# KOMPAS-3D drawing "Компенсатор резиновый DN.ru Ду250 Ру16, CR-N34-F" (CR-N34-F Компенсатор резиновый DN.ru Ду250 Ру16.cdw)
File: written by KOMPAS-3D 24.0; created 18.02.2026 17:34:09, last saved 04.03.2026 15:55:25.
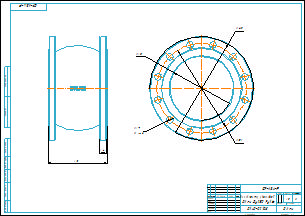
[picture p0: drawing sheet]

Document properties: Типовые: Типовые; Автор: DN.RU; Форматы листов документа: A2; Полное имя файла: CR-N34-F Компенсатор резиновый DN.ru Ду250 Ру16.m3d; Масса: 25; Наименование: Компенсатор резиновый DN.ru Ду250 Ру16; Количество листов документа: 1; Комментарий: D140-02108; Примечание: D140-02108

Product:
- Body: Твердое тело2  | qty 1
    Масса: 70.952857
- Part/product: Компенсатор резиновый DN.ru Ду250 Ру16  | designation CR-N34-F
    Масса: 25
    Раздел спецификации: Прочие изделия
    Комментарий: D140-02108
    Примечание: D140-02108
    additional columns: Типовые

Views: Вид 1, Спереди, Проекционный вид 2
Referenced files in E:\Работа\Зайцев\CR-N34-F Компенсатор резиновый DN.ru ДУ25-300 Ру10-16\DN250_PN16\: CR-N34-F Компенсатор резиновый DN.ru Ду250 Ру16.m3d
Referenced files in E:\Работа\Зайцев\Для компаса\: чертеж DN.ru А3.cdt
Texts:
  CR-N34-F
  чертеж DN.ru А3.cdt
  Компенсатор резиновый
  DN.ru Ду250 Ру16
  Твердое тело2
  Компенсатор резиновый DN.ru Ду250 Ру16
  CR-N34-F Компенсатор резиновый DN.ru Ду250 Ру16
Dimensions and other numbers on the sheet: 0; 3; 2; 4; 230; 24; 405; 350; 250; 27; 12 отв.; 1:2; 1; 25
